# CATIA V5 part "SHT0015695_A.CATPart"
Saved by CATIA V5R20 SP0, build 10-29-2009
Part number: SHT0015695
Revision: A
Definition: 前地脚钣金
Property "单位": "PC"
Bounding box of the stored display mesh (mm): x -134.82 to 134.181, y 258.274 to 308.278, z -502.351 to -487.344
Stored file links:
  C:\TCIC_V5_tmp\catuii\SHT0015695_A.CATPart
  E:\Gao Bingchuan\PDM\CATIA 零件自定义属性_外部_20180629\CATIA 零件自定义属性_外部_20180704.txt
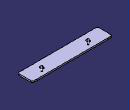
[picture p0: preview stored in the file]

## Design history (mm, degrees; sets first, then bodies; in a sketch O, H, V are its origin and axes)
Set1
  Line1: type Normal, RefPoint {point type OnCurve, Support {line type PtPt, FirstPoint vertex [face of Solid1 | face of Solid1 | face of Solid1], SecondPoint vertex [face of Solid1 | face of Solid1 | face of Solid1]}, Ratio 0.5}, RefSkin face of Solid1, Start -5, End 10
  Line2: type Normal, RefPoint {point type OnCurve, Support {line type PtPt, FirstPoint vertex [face of Solid1 | face of Solid1 | face of Solid1], SecondPoint vertex [face of Solid1 | face of Solid1 | face of Solid1]}, Ratio 0.5}, RefSkin face of Solid1, Start -5, End 10
Body1 (main body)
  Solid1 "实体.24": solid without history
